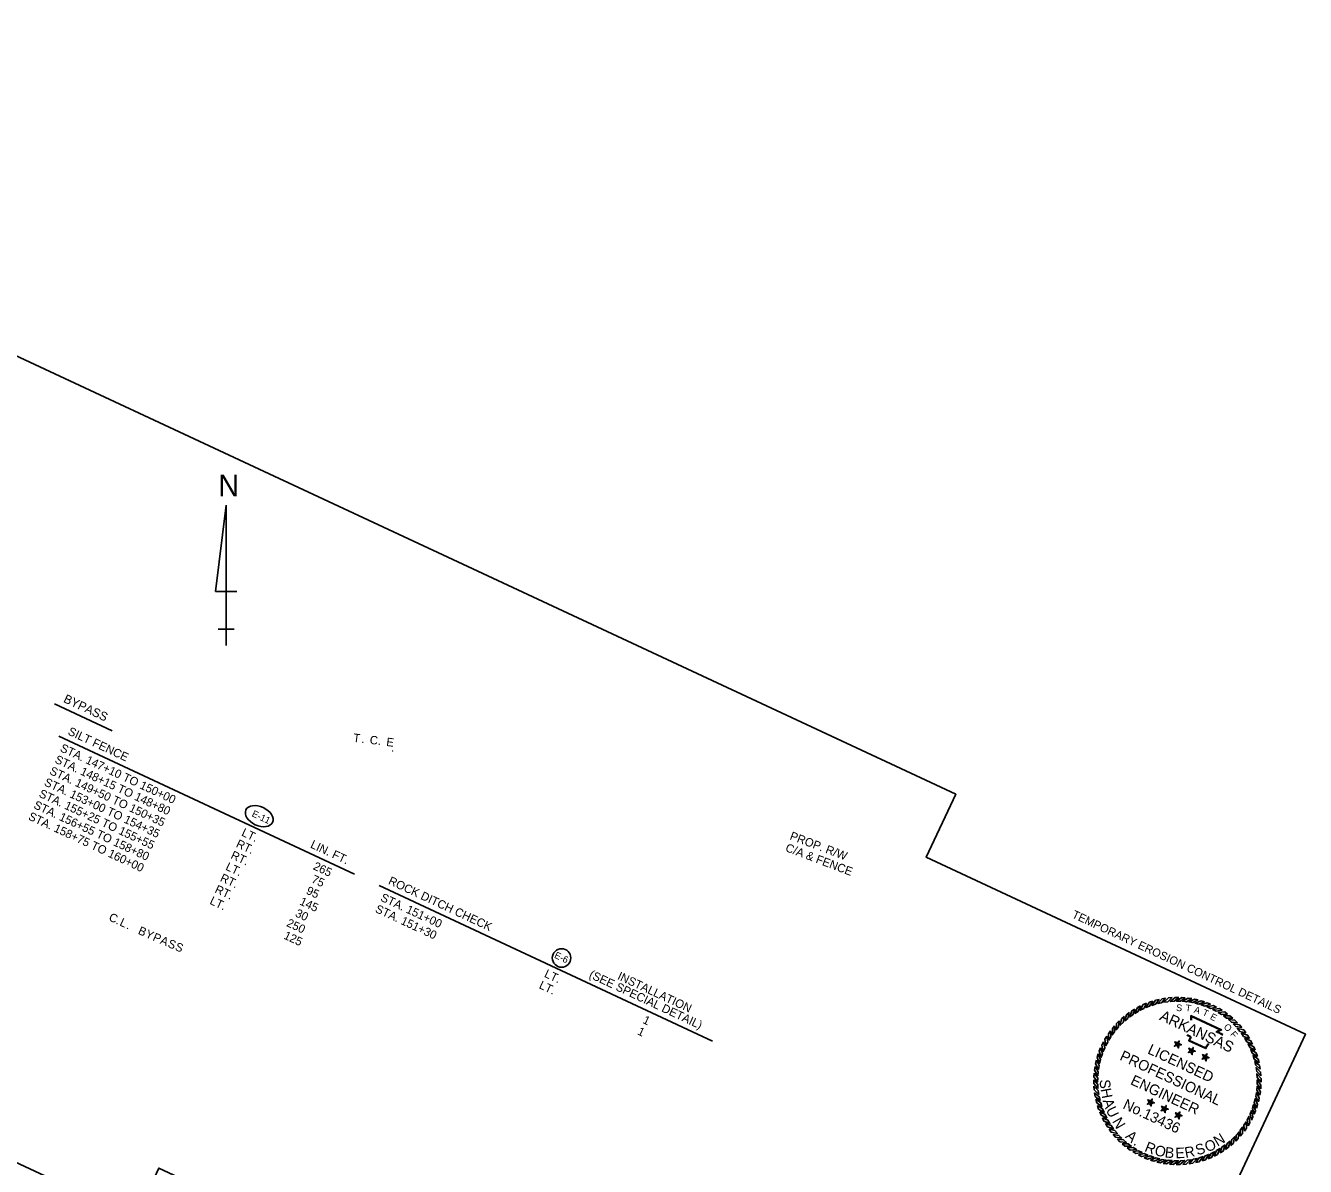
# Model space of a CAD drawing. Extents: x 980231 to 982096, y 1837566 to 1839185.
# Drawn here: x 981183 to 982096, y 1838371 to 1839185 of the extents above; entities that cross this region are included whole.
import ezdxf

# ---------------------------------------------------------------- set-up
doc = ezdxf.new("R2010")
doc.units = 0
for name, color, linetype in [('1', 7, 'Continuous'), ('44', 7, 'Continuous'), ('63', 7, 'Continuous'), ('G-ANNO-SYMB', 7, 'Continuous'), ('G-Border-Sheet', 7, 'Continuous'), ('R_Draft', 7, 'Continuous')]:
    doc.layers.add(name, color=color, linetype=linetype)

msp = doc.modelspace()

# ---------------------------------------------------------------- linework, layer by layer
at = {"layer": '1'}
msp.add_circle((981565.76, 1838520.02), 6.61, dxfattribs=at)
msp.add_ellipse((981350.1, 1838621.12), major_axis=(9.53, -4.45), ratio=0.638788, dxfattribs=at)
at = {"layer": '44'}
for p, q in [((981203.96, 1838701.27), (981245.27, 1838682.01)), ((981207.18, 1838678.15), (981418.16, 1838579.77)), ((981435.72, 1838571.58), (981673.53, 1838460.69))]:
    msp.add_line(p, q, dxfattribs=at)
at = {"layer": '63'}
for p, q in [((981326.55, 1838842.84), (981318.86, 1838781.3)), ((981326.55, 1838742.84), (981326.55, 1838842.84)), ((981326.55, 1838842.84), (981326.55, 1838765.92)), ((981318.86, 1838781.3), (981334.24, 1838781.3)), ((981326.55, 1838742.84), (981326.55, 1838765.92)), ((981326.55, 1838754.38), (981320.78, 1838754.38)), ((981320.78, 1838754.38), (981332.32, 1838754.38)), ((981326.55, 1838742.84), (981326.55, 1838754.38))]:
    msp.add_line(p, q, dxfattribs=at)
at = {"layer": 'G-ANNO-SYMB'}
for points in [[(981983.05, 1838487.73), (981980.69, 1838486.73), (981978.58, 1838482.67), (981981.06, 1838483.9)], [(981987.47, 1838489.28), (981985.04, 1838488.47), (981982.61, 1838484.6), (981985.19, 1838485.63)], [(981992, 1838490.49), (981989.51, 1838489.87), (981986.79, 1838486.19), (981989.43, 1838487.02)], [(981996.61, 1838491.33), (981994.07, 1838490.91), (981991.07, 1838487.46), (981993.78, 1838488.08)], [(982001.27, 1838491.81), (981998.71, 1838491.59), (981995.45, 1838488.39), (981998.19, 1838488.79)], [(982005.95, 1838491.92), (982003.38, 1838491.91), (981999.88, 1838488.97), (982002.65, 1838489.15)], [(982010.63, 1838491.67), (982008.07, 1838491.85), (982004.34, 1838489.2), (982007.12, 1838489.17)], [(982015.27, 1838491.05), (982012.73, 1838491.43), (982008.81, 1838489.08), (982011.57, 1838488.83)], [(982019.85, 1838490.07), (982017.35, 1838490.65), (982013.26, 1838488.61), (982015.99, 1838488.14)], [(982024.34, 1838488.73), (982021.89, 1838489.5), (982017.65, 1838487.79), (982020.34, 1838487.11)], [(982028.71, 1838487.04), (982026.33, 1838488.01), (982021.97, 1838486.63), (982024.6, 1838485.74)], [(981966.99, 1838478.21), (981965.05, 1838476.54), (981964.3, 1838472.03), (981966.28, 1838473.96)], [(981970.71, 1838481.06), (981968.65, 1838479.54), (981967.54, 1838475.1), (981969.67, 1838476.88)], [(981974.65, 1838483.6), (981972.47, 1838482.25), (981971.02, 1838477.91), (981973.28, 1838479.51)], [(981978.77, 1838485.83), (981976.49, 1838484.65), (981974.7, 1838480.44), (981977.08, 1838481.86)], [(982032.93, 1838485.01), (982030.64, 1838486.16), (982026.18, 1838485.14), (982028.73, 1838484.04)], [(982036.98, 1838482.66), (982034.79, 1838483.99), (982030.27, 1838483.31), (982032.72, 1838482.03)], [(982040.84, 1838480), (982038.75, 1838481.5), (982034.19, 1838481.18), (982036.54, 1838479.7)], [(982044.47, 1838477.05), (982042.51, 1838478.7), (982037.94, 1838478.74), (982040.16, 1838477.09)], [(981960.27, 1838471.7), (981958.62, 1838469.73), (981958.58, 1838465.16), (981960.24, 1838467.38)], [(981963.5, 1838475.09), (981961.7, 1838473.26), (981961.3, 1838468.71), (981963.13, 1838470.79)], [(982047.87, 1838473.82), (982046.04, 1838475.62), (982041.49, 1838476.02), (982043.57, 1838474.19)], [(982050.99, 1838470.33), (982049.32, 1838472.27), (982044.81, 1838473.02), (982046.74, 1838471.04)], [(982053.84, 1838466.61), (982052.32, 1838468.67), (982047.88, 1838469.78), (982049.66, 1838467.65)], [(981952.31, 1838460.15), (981951.16, 1838457.86), (981952.19, 1838453.4), (981953.28, 1838455.95)], [(981954.66, 1838464.2), (981953.33, 1838462.01), (981954.01, 1838457.49), (981955.29, 1838459.94)], [(981957.32, 1838468.06), (981955.82, 1838465.98), (981956.14, 1838461.41), (981957.62, 1838463.76)], [(982005.2, 1838458.41), (982005.01, 1838459.43), (982003.21, 1838460.27), (982004.17, 1838458.54)], [(982005.2, 1838458.41), (982006.11, 1838458.92), (982006.36, 1838460.88), (982005.01, 1838459.43)], [(982056.38, 1838462.67), (982055.03, 1838464.85), (982050.69, 1838466.3), (982052.29, 1838464.04)], [(982058.61, 1838458.55), (982057.43, 1838460.83), (982053.22, 1838462.62), (982054.64, 1838460.24)], [(981948.6, 1838451.56), (981947.82, 1838449.11), (981949.53, 1838444.87), (981950.21, 1838447.56)], [(981950.28, 1838455.93), (981949.32, 1838453.55), (981950.69, 1838449.19), (981951.58, 1838451.82)], [(982005.2, 1838458.41), (982004.17, 1838458.54), (982002.82, 1838457.09), (982004.76, 1838457.47)], [(982005.2, 1838458.41), (982004.76, 1838457.47), (982005.72, 1838455.73), (982005.97, 1838457.7)], [(982005.2, 1838458.41), (982005.97, 1838457.7), (982007.91, 1838458.08), (982006.11, 1838458.92)], [(982015.09, 1838453.8), (982014.06, 1838453.93), (982012.71, 1838452.48), (982014.65, 1838452.86)], [(982015.09, 1838453.8), (982014.89, 1838454.82), (982013.1, 1838455.66), (982014.06, 1838453.93)], [(982015.09, 1838453.8), (982014.65, 1838452.86), (982015.61, 1838451.12), (982015.85, 1838453.09)], [(982015.09, 1838453.8), (982016, 1838454.31), (982016.24, 1838456.27), (982014.89, 1838454.82)], [(982015.09, 1838453.8), (982015.85, 1838453.09), (982017.8, 1838453.47), (982016, 1838454.31)], [(982024.98, 1838449.19), (982024.78, 1838450.21), (982022.98, 1838451.05), (982023.94, 1838449.32)], [(982024.98, 1838449.19), (982025.89, 1838449.7), (982026.13, 1838451.66), (982024.78, 1838450.21)], [(982060.51, 1838454.27), (982059.51, 1838456.63), (982055.45, 1838458.74), (982056.68, 1838456.26)], [(982062.06, 1838449.85), (982061.25, 1838452.29), (982057.38, 1838454.71), (982058.41, 1838452.14)], [(982063.26, 1838445.32), (982062.65, 1838447.81), (982058.97, 1838450.53), (982059.8, 1838447.89)], [(981946.27, 1838442.49), (981945.89, 1838439.95), (981948.24, 1838436.03), (981948.49, 1838438.79)], [(981947.26, 1838447.07), (981946.67, 1838444.57), (981948.71, 1838440.48), (981949.18, 1838443.21)], [(982024.98, 1838449.19), (982023.94, 1838449.32), (982022.59, 1838447.87), (982024.54, 1838448.25)], [(982024.98, 1838449.19), (982024.54, 1838448.25), (982025.5, 1838446.51), (982025.74, 1838448.48)], [(982024.98, 1838449.19), (982025.74, 1838448.48), (982027.68, 1838448.86), (982025.89, 1838449.7)], [(982064.11, 1838440.72), (982063.69, 1838443.25), (982060.24, 1838446.25), (982060.86, 1838443.54)], [(982064.59, 1838436.06), (982064.37, 1838438.61), (982061.17, 1838441.87), (982061.57, 1838439.13)], [(981945.4, 1838433.17), (981945.41, 1838430.6), (981948.35, 1838427.1), (981948.17, 1838429.87)], [(981945.65, 1838437.85), (981945.47, 1838435.29), (981948.12, 1838431.56), (981948.16, 1838434.34)], [(982064.7, 1838431.37), (982064.69, 1838433.94), (982061.75, 1838437.44), (982061.93, 1838434.68)], [(982064.45, 1838426.7), (982064.63, 1838429.25), (982061.98, 1838432.98), (982061.95, 1838430.21)], [(981945.51, 1838428.49), (981945.73, 1838425.93), (981948.93, 1838422.67), (981948.53, 1838425.41)], [(981945.99, 1838423.83), (981946.41, 1838421.29), (981949.86, 1838418.29), (981949.25, 1838421)], [(982062.85, 1838417.47), (982063.43, 1838419.97), (982061.39, 1838424.06), (982060.92, 1838421.33)], [(982063.83, 1838422.05), (982064.21, 1838424.59), (982061.86, 1838428.51), (982061.61, 1838425.75)], [(981946.84, 1838419.22), (981947.45, 1838416.73), (981951.13, 1838414.01), (981950.3, 1838416.65)], [(981948.04, 1838414.69), (981948.85, 1838412.26), (981952.73, 1838409.83), (981951.7, 1838412.41)], [(981985.9, 1838417.01), (981984.86, 1838417.14), (981983.51, 1838415.69), (981985.46, 1838416.07)], [(981985.9, 1838417.01), (981985.7, 1838418.03), (981983.9, 1838418.87), (981984.86, 1838417.14)], [(981985.9, 1838417.01), (981985.46, 1838416.07), (981986.42, 1838414.33), (981986.66, 1838416.3)], [(981985.9, 1838417.01), (981986.81, 1838417.52), (981987.05, 1838419.48), (981985.7, 1838418.03)], [(981985.9, 1838417.01), (981986.66, 1838416.3), (981988.6, 1838416.68), (981986.81, 1838417.52)], [(981995.78, 1838412.4), (981995.59, 1838413.42), (981993.79, 1838414.26), (981994.75, 1838412.53)], [(981995.78, 1838412.4), (981996.7, 1838412.9), (981996.94, 1838414.87), (981995.59, 1838413.42)], [(982059.82, 1838408.61), (982060.79, 1838410.99), (982059.41, 1838415.35), (982058.52, 1838412.73)], [(982061.51, 1838412.98), (982062.28, 1838415.43), (982060.57, 1838419.67), (982059.89, 1838416.98)], [(981949.6, 1838410.27), (981950.59, 1838407.91), (981954.65, 1838405.8), (981953.42, 1838408.28)], [(981951.49, 1838405.99), (981952.67, 1838403.71), (981956.88, 1838401.92), (981955.46, 1838404.3)], [(981995.78, 1838412.4), (981994.75, 1838412.53), (981993.4, 1838411.08), (981995.34, 1838411.46)], [(981995.78, 1838412.4), (981995.34, 1838411.46), (981996.31, 1838409.72), (981996.55, 1838411.69)], [(981995.78, 1838412.4), (981996.55, 1838411.69), (981998.49, 1838412.07), (981996.7, 1838412.9)], [(982005.67, 1838407.79), (982004.64, 1838407.92), (982003.29, 1838406.47), (982005.23, 1838406.85)], [(982005.67, 1838407.79), (982005.47, 1838408.81), (982003.68, 1838409.65), (982004.64, 1838407.92)], [(982005.67, 1838407.79), (982005.23, 1838406.85), (982006.19, 1838405.11), (982006.43, 1838407.08)], [(982005.67, 1838407.79), (982006.58, 1838408.29), (982006.82, 1838410.26), (982005.47, 1838408.81)], [(982005.67, 1838407.79), (982006.43, 1838407.08), (982008.38, 1838407.46), (982006.58, 1838408.29)], [(982055.44, 1838400.34), (982056.77, 1838402.53), (982056.09, 1838407.06), (982054.81, 1838404.6)], [(982057.79, 1838404.39), (982058.94, 1838406.68), (982057.92, 1838411.14), (982056.82, 1838408.59)], [(981953.72, 1838401.87), (981955.07, 1838399.69), (981959.41, 1838398.24), (981957.81, 1838400.5)], [(981956.26, 1838397.93), (981957.78, 1838395.87), (981962.22, 1838394.76), (981960.45, 1838396.89)], [(982046.6, 1838389.46), (982048.4, 1838391.28), (982048.8, 1838395.84), (982046.97, 1838393.75)], [(982049.83, 1838392.85), (982051.48, 1838394.81), (982051.52, 1838399.38), (982049.87, 1838397.16)], [(982052.78, 1838396.48), (982054.28, 1838398.57), (982053.96, 1838403.13), (982052.48, 1838400.78)], [(981959.11, 1838394.21), (981960.79, 1838392.27), (981965.3, 1838391.52), (981963.36, 1838393.5)], [(981962.24, 1838390.73), (981964.06, 1838388.92), (981968.62, 1838388.52), (981966.53, 1838390.35)], [(981965.63, 1838387.49), (981967.59, 1838385.84), (981972.16, 1838385.8), (981969.94, 1838387.46)], [(982035.45, 1838380.94), (982037.63, 1838382.29), (982039.08, 1838386.63), (982036.82, 1838385.03)], [(982039.39, 1838383.48), (982041.45, 1838385), (982042.56, 1838389.44), (982040.43, 1838387.67)], [(982043.11, 1838386.33), (982045.05, 1838388.01), (982045.8, 1838392.52), (982043.82, 1838390.58)], [(981969.26, 1838384.54), (981971.35, 1838383.04), (981975.91, 1838383.36), (981973.56, 1838384.84)], [(981973.12, 1838381.88), (981975.31, 1838380.55), (981979.84, 1838381.23), (981977.38, 1838382.52)], [(981977.17, 1838379.53), (981979.46, 1838378.38), (981983.92, 1838379.41), (981981.37, 1838380.5)], [(981981.39, 1838377.5), (981983.77, 1838376.54), (981988.13, 1838377.91), (981985.51, 1838378.8)], [(981985.76, 1838375.82), (981988.21, 1838375.04), (981992.45, 1838376.75), (981989.76, 1838377.43)], [(982013.5, 1838373.21), (982016.03, 1838373.63), (982019.03, 1838377.08), (982016.32, 1838376.47)], [(982018.1, 1838374.06), (982020.59, 1838374.67), (982023.31, 1838378.35), (982020.67, 1838377.52)], [(982022.63, 1838375.26), (982025.07, 1838376.07), (982027.49, 1838379.95), (982024.92, 1838378.92)], [(982027.05, 1838376.82), (982029.41, 1838377.81), (982031.52, 1838381.87), (982029.04, 1838380.64)], [(982031.33, 1838378.71), (982033.61, 1838379.89), (982035.4, 1838384.1), (982033.02, 1838382.68)], [(981990.25, 1838374.48), (981992.75, 1838373.89), (981996.84, 1838375.93), (981994.11, 1838376.4)], [(981994.83, 1838373.49), (981997.37, 1838373.11), (982001.29, 1838375.46), (981998.53, 1838375.71)], [(981999.48, 1838372.87), (982002.03, 1838372.69), (982005.76, 1838375.34), (982002.99, 1838375.38)], [(982004.15, 1838372.62), (982006.72, 1838372.63), (982010.22, 1838375.57), (982007.46, 1838375.39)], [(982008.84, 1838372.73), (982011.39, 1838372.95), (982014.65, 1838376.15), (982011.91, 1838375.75)]]:
    msp.add_lwpolyline(points, close=True, dxfattribs=at)
for points in [[(982014.69, 1838475.55), (982014.7, 1838478.87), (982036.52, 1838468.71), (982033.63, 1838467.27), (982035.12, 1838466.6), (982036.36, 1838466.04), (982037.53, 1838465.33)], [(982015.07, 1838475.55), (982015.08, 1838478.27), (982035.64, 1838468.7), (982032.74, 1838467.26), (982034.96, 1838466.26), (982036.18, 1838465.7), (982037.34, 1838465)], [(982027.54, 1838458.43), (982027.02, 1838458.31), (982026.69, 1838457.91), (982026.04, 1838456.84), (982025.34, 1838455.33), (982013.16, 1838461.01), (982014.11, 1838463.04), (982014.32, 1838463.49), (982013.9, 1838463.88), (982012.17, 1838464.68), (982012.08, 1838465.3)], [(982027.44, 1838458.8), (982026.81, 1838458.64), (982026.38, 1838458.13), (982025.7, 1838457.02), (982025.15, 1838455.84), (982013.67, 1838461.19), (982014.46, 1838462.88), (982014.79, 1838463.59), (982014.11, 1838464.2), (982012.51, 1838464.94), (982012.46, 1838465.35)]]:
    msp.add_lwpolyline(points, dxfattribs=at)
at = {"layer": 'G-Border-Sheet'}
msp.add_lwpolyline([(980671.38, 1839184.86), (981846.87, 1838636.72), (981825.93, 1838591.82), (982096.33, 1838465.73), (981897.02, 1838038.3), (981572.45, 1838189.65), (981589.08, 1838225.31), (981278.52, 1838370.12), (981261.89, 1838334.46), (981017.57, 1838448.39), (981048.11, 1838513.87), (980662.93, 1838693.49), (980632.39, 1838628), (980451.13, 1838712.53)], close=True, dxfattribs=at)
msp.add_lwpolyline([(980671.38, 1839184.86), (981846.87, 1838636.72), (981825.93, 1838591.82), (982096.33, 1838465.73), (981897.02, 1838038.3), (981572.45, 1838189.65), (981589.08, 1838225.31), (981278.52, 1838370.12), (981261.89, 1838334.46), (981017.57, 1838448.39), (981048.11, 1838513.87), (980662.93, 1838693.49), (980632.39, 1838628), (980451.13, 1838712.53)], close=True, dxfattribs=at)
msp.add_lwpolyline([(980671.38, 1839184.86), (981846.87, 1838636.72), (981825.93, 1838591.82), (982096.33, 1838465.73), (981897.02, 1838038.3), (981572.45, 1838189.65), (981589.08, 1838225.31), (981278.52, 1838370.12), (981261.89, 1838334.46), (981017.57, 1838448.39), (981048.11, 1838513.87), (980662.93, 1838693.49), (980632.39, 1838628), (980451.13, 1838712.53)], close=True, dxfattribs=at)

# ---------------------------------------------------------------- texts
at = {"layer": '1'}
for s, height, rotation, p in [('E-11', 4.8, 334.99998, (981344.39, 1838621.18)), ('TEMPORARY EROSION CONTROL DETAILS', 5.8625, 335, (981929.3, 1838548.99)), ('E-6 ', 4.8, 335, (981560.16, 1838520.33))]:
    msp.add_text(s, height=height, rotation=rotation, dxfattribs=at).set_placement(p)
at = {"layer": '44'}
for s, height, rotation, p in [('BYPASS', 6.25, 335, (981209.95, 1838702.65)), ('SILT FENCE      ', 6, 334.99998, (981213.11, 1838679.53)), ('STA. 147+10 TO 150+00', 6, 334.99998, (981207.55, 1838667.6)), ('STA. 148+15 TO 148+80', 6, 334.99998, (981203.76, 1838659.49)), ('STA. 149+50 TO 150+35', 6, 334.99998, (981199.98, 1838651.38)), ('STA. 153+00 TO 154+35', 6, 334.99998, (981196.2, 1838643.27)), ('STA. 155+25 TO 155+55', 6, 334.99998, (981192.42, 1838635.16)), ('STA. 158+75 TO 160+00', 6, 334.99998, (981184.86, 1838618.94)), ('STA. 156+55 TO 158+80', 6, 334.99998, (981188.64, 1838627.05)), ('LT.', 6, 334.99998, (981336.95, 1838607.42)), ('RT.', 6, 334.99998, (981329.26, 1838591.26)), ('RT.', 6, 334.99998, (981333.04, 1838599.37)), ('LIN. FT.', 6, 334.99998, (981386.09, 1838598.87)), ('LT.', 6, 334.99998, (981325.6, 1838583.09)), ('265', 6, 334.99998, (981388.05, 1838583.41)), ('RT.', 6, 334.99998, (981321.69, 1838575.04)), ('75', 6, 334.99998, (981386.84, 1838574.1)), ('ROCK DITCH CHECK', 6, 335, (981441.65, 1838572.96)), ('RT.', 6, 334.99998, (981317.91, 1838566.93)), ('95', 6, 334.99998, (981383.06, 1838565.99)), ('LT.', 6, 334.99998, (981314.26, 1838558.76)), ('145', 6, 334.99998, (981378.38, 1838558.3)), ('STA. 151+00', 6, 334.99998, (981436.09, 1838561.03)), ('30', 6, 334.99998, (981375.26, 1838549.88)), ('STA. 151+30', 6, 334.99998, (981432.3, 1838552.92)), ('250', 6, 334.99998, (981369.04, 1838542.91)), ('125', 6, 334.99998, (981367.03, 1838533.97)), ('LT.', 6, 334.99998, (981552.93, 1838506.71)), ('(SEE SPECIAL DETAIL)', 6, 335, (981584.83, 1838506.19)), ('INSTALLATION', 6, 335, (981605.11, 1838505.02)), ('LT.', 6, 334.99998, (981549.15, 1838498.6)), ('1', 6, 334.99998, (981623.14, 1838473.78)), ('1', 6, 334.99998, (981619.36, 1838465.67))]:
    msp.add_text(s, height=height, rotation=rotation, dxfattribs=at).set_placement(p)
at = {"layer": '63'}
msp.add_text('N', height=15.38, dxfattribs=at).set_placement((981320.92, 1838849.25))
at = {"layer": 'G-ANNO-SYMB'}
for s, height, rotation, p in [('S', 4.75, 354.77256, (982004, 1838482.28)), ('T', 4.75, 351.90148, (982010.61, 1838482.19)), ('ARKANSAS', 7.747, 335, (981991.7, 1838476.1)), ('A', 4.75, 343.67877, (982016.47, 1838481.11)), ('T', 4.75, 336.47887, (982022.43, 1838479.38)), ('E', 4.75, 331.67203, (982027.87, 1838476.68)), ('O', 4.75, 316.2218, (982037.63, 1838470.33)), ('F', 4.75, 310.36282, (982042.37, 1838465.36)), ('PROFESSIONAL', 7.5, 335, (981963.33, 1838447.59)), ('LICENSED', 7.5, 335, (981983.2, 1838452.16)), ('S', 7.5, 273.16364, (981949.57, 1838433.21)), ('ENGINEER', 7.5, 335, (981970.98, 1838430.18)), ('H', 7.5, 280.61905, (981950.18, 1838426.44)), ('A', 7.5, 288.44722, (981951.61, 1838418.22)), ('U', 7.5, 295.90262, (981953.78, 1838411.81)), ('No.13436', 7.47, 335, (981965.57, 1838412.98)), ('N', 7.5, 299.93262, (981958.27, 1838403.55)), ('A', 7.5, 318.09908, (981967.4, 1838392.2)), ('.', 7.5, 326.30002, (981973.15, 1838387.1)), ('R', 7.5, 338.22866, (981981.09, 1838382.36)), ('O', 7.5, 346.42961, (981988.25, 1838379.55)), ('S', 7.5, 18.48784, (982019.3, 1838379.11)), ('O', 7.5, 19.77573, (982026.07, 1838381.44)), ('N', 7.5, 31.10067, (982033.64, 1838385.36)), ('B', 7.5, 353.88501, (981995.73, 1838377.82)), ('E', 7.5, 2.83149, (982003.74, 1838377.07)), ('R', 7.5, 10.65967, (982010.89, 1838377.4))]:
    msp.add_text(s, height=height, rotation=rotation, dxfattribs=at).set_placement(p)
at = {"layer": 'R_Draft'}
for s, rotation, p in [('T', 352.8891, (981416.85, 1838674.17)), ('C', 352.8891, (981428.66, 1838672.7)), ('.', 352.8891, (981422.76, 1838673.44)), ('.', 352.8891, (981434.57, 1838671.96)), ('E', 352.8891, (981440.48, 1838671.23)), ('.', 278.1953, (981444.58, 1838668.65)), ('PROP. R/W', 339.24286, (981728.09, 1838604.72)), ('C/A & FENCE', 339.24286, (981724.9, 1838596.31)), ('C', 334.74843, (981242.23, 1838547.03)), ('.', 335.03116, (981247.39, 1838544.6)), ('L', 335.17723, (981250.05, 1838543.35)), ('.', 335.44582, (981254.97, 1838541.08)), ('B', 335.89111, (981263.14, 1838537.36)), ('Y', 336.17384, (981268.34, 1838535.03)), ('P', 336.46127, (981273.64, 1838532.69)), ('A', 336.744, (981278.86, 1838530.42)), ('S', 337.03615, (981284.28, 1838528.09)), ('S', 337.31887, (981289.52, 1838525.87))]:
    msp.add_text(s, height=6, rotation=rotation, dxfattribs=at).set_placement(p)

doc.saveas('drawing.dxf')
